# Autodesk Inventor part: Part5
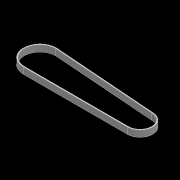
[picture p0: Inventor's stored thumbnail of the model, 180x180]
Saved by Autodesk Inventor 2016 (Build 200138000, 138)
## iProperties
Created: 2017-04
Part Number: Part5
Material: Generic
Document SubType Name: Modeling
Designer: Sigit
Density: 1 g/cm^3
Appearance: Default
Author: Sigit
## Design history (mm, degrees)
sketch "Sketch1"
  geometry: L1 (0, 48.511)-(323.623, 24.255) reference; L2 (0, -48.511)-(323.623, -48.511) reference; L3 (323.737, 27.255)-(0.114, 51.51); L4 (0, -51.51)-(323.623, -51.511); A1 r 48.511 centre (0, 0) between (0, 48.511) and (0, -48.511) reference; A2 r 36.383 centre (323.623, -12.128) between (323.623, -48.511) and (323.623, 24.255) reference; A3 r 51.511 centre (0, 0) between (0.114, 51.51) and (0, -51.51); A4 r 39.383 centre (323.623, -12.128) between (323.623, -51.511) and (323.737, 27.255); 1 further point
  constraints: 4 end point, 4 point on circle, 2 centre point, 3 other
  dimensions: "d0" = 3 distance between parallel lines of L1 L3
  node "Reference1"
  node "Reference2"
  node "Reference3"
  node "Reference4"
workplane "Work Plane1"
workplane "Work Plane2"
extrude "Extrusion1" new body sketch "Sketch1" stored distance "d1" = 10; taper "d2" = 0 deg
fillet "Fillet1" dims "d3" = 0.1
body "Solid1"
